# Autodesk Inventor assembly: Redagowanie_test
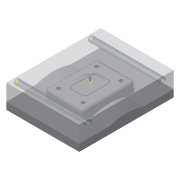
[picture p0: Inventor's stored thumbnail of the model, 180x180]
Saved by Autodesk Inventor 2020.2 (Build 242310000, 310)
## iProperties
Created: 2015-11
Part Number: Redagowanie_test
Document SubType Name: Assembly
Designer: F.Stasiak
Catalog Web Link: www.expertbooks.pl
Manager: www.cadconsulting.pl
Company: Fabian Stasiak CAD Consulting
Author: F.Stasiak
Subject: Zbiór ćwiczeń. Autodesk Inventor 2020. Kurs Professional
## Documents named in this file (4)
- C:\2020_Kurs_Professional\R6 Formy\Redagowanie\Redagowanie_test.iam
- C:\2020_Kurs_Professional\R6 Formy\Redagowanie\Redagowanie_test_Pokrywa_AS100_LY.iam
- C:\2020_Kurs_Professional\R6 Formy\Redagowanie\Redagowanie_test_RG.ipt
- C:\2020_Kurs_Professional\R6 Formy\Redagowanie\Redagowanie_test_CH.ipt
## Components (3 placed, 3 different names)
1. Redagowanie_test_Pokrywa_AS100_LY:1 [sub-assembly] — Równoległy:1, Równoległy:2, Równoległy:3
2. Redagowanie_test_RG:1
3. Redagowanie_test_CH:1
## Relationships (3: Flush 3)
- Równoległy:1 [Flush]: Redagowanie_test_Pokrywa_AS100_LY:1
- Równoległy:2 [Flush]: Redagowanie_test_Pokrywa_AS100_LY:1
- Równoległy:3 [Flush]: Redagowanie_test_Pokrywa_AS100_LY:1
